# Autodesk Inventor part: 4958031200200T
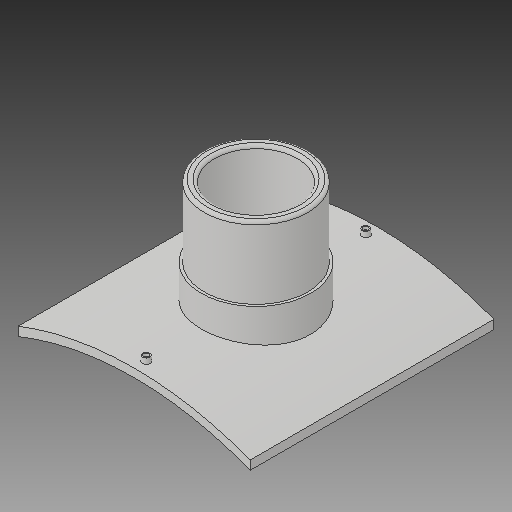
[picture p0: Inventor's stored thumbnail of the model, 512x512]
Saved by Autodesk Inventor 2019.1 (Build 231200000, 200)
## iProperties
Created: 2017-10
Part Number: 4958031200200T
Material: Generic
Description: PLASSON BRANCH SADDLE 1200x200
Document SubType Name: Modeling
Designer: KIM
Mass: 2754.05 g
Surface Area: 3037.44 cm^2
Volume: 2754.05 cm^3
Density: 1 g/cm^3
Appearance: Default
Author: KIM
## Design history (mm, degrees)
derived "495803.ipt"
feature "Solid1::495803.ipt"
tag "TaggingFeature1"
body "Solid1"
other parameters: "d1" = 16, "d2" = 447, "d4" = 0, "d12" = 625.6, "d13" = 14, "d14" = 211.5, "d16" = 5 deg, "d18" = 4, "d19" = 14, "d20" = 0, "d21" = 3, "d22" = 0, "d23" = 814, "d25" = 16, "d28" = 0, "d29" = 9.6, "d31" = 0, "d32" = 99, "d33" = 0, "d34" = 12, "d37" = 138.6, "d38" = 0, "d39" = 6, "B_" = 447, "H_" = 198, "x_" = 16, "D_" = 16
